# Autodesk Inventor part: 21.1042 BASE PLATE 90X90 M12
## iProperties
Created: 2007-03
Part Number: 21.1042 BASE PLATE 90X90 M12
Document SubType Name: Modeling
Designer: Andy Moles
Material: Aluminum-6061
Mass: 306.083 g
Surface Area: 230.819 cm^2
Volume: 112.946 cm^3
Density: 2.71 g/cm^3
Author: Andy Moles
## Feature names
1. Extrusion1
2. Fillet1
3. Hole1
4. Hole2
5. Hole3
6. Hole4
7. Fillet2
